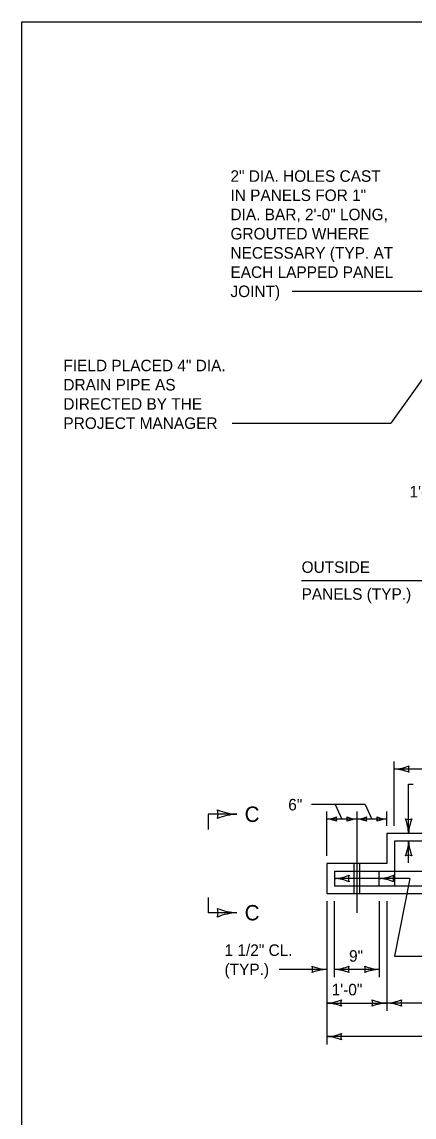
# Model space of a CAD drawing. Extents: x 49991.4 to 50021, y 49987.6 to 50011.4.
# Drawn here: x 49999.38 to 50001.43, y 49993.3 to 49999 of the extents above; entities that cross this region are included whole.
import ezdxf

# ---------------------------------------------------------------- set-up
doc = ezdxf.new("R2010")
doc.units = 0
for name, color, linetype in [('Level 1', 7, 'Continuous'), ('Level 2', 7, 'Continuous'), ('Level 3', 7, 'Continuous'), ('Level 4', 7, 'Continuous'), ('Level 5', 7, 'Continuous'), ('Level 6', 7, 'Continuous')]:
    doc.layers.add(name, color=color, linetype=linetype)

msp = doc.modelspace()

# ---------------------------------------------------------------- linework, layer by layer
at = {"layer": 'Level 1'}
for p, q in [((50003.3142, 49994.7753), (50001.283, 49994.7753)), ((50001.283, 49994.7753), (50001.283, 49994.619)), ((50001.323, 49994.7352), (50001.323, 49994.5029)), ((50003.2741, 49994.7352), (50001.323, 49994.7352)), ((50001.283, 49994.619), (50000.9705, 49994.619)), ((50000.9705, 49994.619), (50000.9705, 49994.4628)), ((50001.0105, 49994.579), (50001.0105, 49994.5029)), ((50001.0105, 49994.579), (50001.6735, 49994.579)), ((50001.2428, 49994.5029), (50001.2428, 49994.579)), ((50000.9705, 49994.4628), (50003.6267, 49994.4628)), ((50001.0105, 49994.5029), (50003.5866, 49994.5029))]:
    msp.add_line(p, q, dxfattribs=at)
msp.add_lwpolyline([(49999.3835, 49998.9992), (50016.7501, 49998.9992), (50016.7501, 49987.7988), (49999.3835, 49987.7988)], close=True, dxfattribs=at)
at = {"layer": 'Level 3'}
for p, q in [((50000.7897, 49997.5969), (50001.6157, 49997.5969)), ((50001.5149, 49997.2046), (50001.3035, 49996.9108)), ((50000.4775, 49996.9108), (50001.3035, 49996.9108)), ((50000.8395, 49996.0916), (50001.7038, 49996.0916)), ((50001.3223, 49994.8153), (50001.3223, 49995.1502)), ((50003.2753, 49995.1102), (50001.3223, 49995.1102)), ((50001.3969, 49995.031), (50001.42, 49995.031)), ((50001.3969, 49994.7753), (50001.3969, 49995.031)), ((50001.17, 49994.9252), (50000.8914, 49994.9252)), ((50001.0136, 49994.9252), (50001.0486, 49994.8502)), ((50001.17, 49994.9252), (50001.205, 49994.8502)), ((50000.9706, 49994.659), (50000.9706, 49994.8902)), ((50001.2832, 49994.8153), (50001.2832, 49994.8902)), ((50001.1268, 49994.8502), (50000.9706, 49994.8502)), ((50001.2832, 49994.8502), (50001.1268, 49994.8502)), ((50001.3969, 49994.6228), (50001.3969, 49994.7352)), ((50001.4028, 49994.541), (50001.0105, 49994.541)), ((50001.4028, 49994.541), (50001.323, 49994.1368)), ((50000.9705, 49994.4228), (50000.9705, 49993.6777)), ((50001.0097, 49994.4228), (50001.0097, 49994.0278)), ((50001.2441, 49994.4228), (50001.2441, 49994.0278)), ((50001.283, 49994.4228), (50001.283, 49993.8527)), ((50001.323, 49994.1368), (50001.5507, 49994.1368)), ((50000.9705, 49994.0678), (50000.7221, 49994.0678)), ((50001.2441, 49994.0678), (50001.0097, 49994.0678)), ((50000.9705, 49993.8927), (50001.283, 49993.8927)), ((50003.3142, 49993.8927), (50001.283, 49993.8927)), ((50003.6267, 49993.7177), (50000.9705, 49993.7177))]:
    msp.add_line(p, q, dxfattribs=at)
for centre, radius, start, end in [((50001.3131, 49995.3323), 0.2223, 272.3605, 292.544), ((50001.3108, 49994.8775), 0.233, 67.9228, 87.1727), ((50001.4505, 49995.1102), 0.0548, 162.1388, 197.8612), ((50000.3322, 49994.8754), 0.073, 342.1388, 17.8612), ((50000.5185, 49995.1857), 0.3107, 247.9228, 267.1727), ((50000.5154, 49994.5792), 0.2964, 92.3605, 112.544), ((50000.9645, 49994.9983), 0.1482, 272.3605, 292.544), ((50001.056, 49994.8502), 0.0365, 162.1388, 197.8612), ((50001.0413, 49994.8502), 0.0365, 342.1388, 17.8612), ((50001.1345, 49995.0053), 0.1553, 247.9228, 267.1727), ((50001.1207, 49994.9983), 0.1482, 272.3605, 292.544), ((50001.2123, 49994.8502), 0.0365, 162.1388, 197.8612), ((50001.1977, 49994.8502), 0.0365, 342.1388, 17.8612), ((50001.2908, 49995.0053), 0.1553, 247.9228, 267.1727), ((50000.9629, 49994.6951), 0.1553, 67.9228, 87.1727), ((50001.1329, 49994.7021), 0.1482, 92.3605, 112.544), ((50001.1191, 49994.6951), 0.1553, 67.9228, 87.1727), ((50001.2893, 49994.7021), 0.1482, 92.3605, 112.544), ((50001.3969, 49994.9035), 0.0548, 252.1388, 287.8612), ((50001.1642, 49994.7638), 0.233, 2.8273, 22.0772), ((50001.619, 49994.7661), 0.2223, 157.456, 177.6395), ((50001.1748, 49994.7444), 0.2223, 337.456, 357.6395), ((50001.6296, 49994.7467), 0.233, 182.8273, 202.0772), ((50001.3969, 49994.607), 0.0548, 72.1388, 107.8612), ((50001.0013, 49994.7631), 0.2223, 272.3605, 292.544), ((50000.999, 49994.3083), 0.233, 67.9228, 87.1727), ((50001.1387, 49994.541), 0.0548, 162.1388, 197.8612), ((50001.2336, 49994.7631), 0.2223, 272.3605, 292.544), ((50001.2313, 49994.3083), 0.233, 67.9228, 87.1727), ((50001.371, 49994.541), 0.0548, 162.1388, 197.8612), ((50000.3322, 49994.3628), 0.073, 342.1388, 17.8612), ((50000.5185, 49994.6731), 0.3107, 247.9228, 267.1727), ((50000.5154, 49994.0666), 0.2964, 92.3605, 112.544), ((50000.8423, 49994.0678), 0.0548, 342.1388, 17.8612), ((50000.982, 49994.3005), 0.233, 247.9228, 267.1727), ((50000.9797, 49993.8457), 0.2223, 92.3605, 112.544), ((50001.0005, 49994.2899), 0.2223, 272.3605, 292.544), ((50000.9982, 49993.8351), 0.233, 67.9228, 87.1727), ((50001.1379, 49994.0678), 0.0548, 162.1388, 197.8612), ((50001.1159, 49994.0678), 0.0548, 342.1388, 17.8612), ((50001.2556, 49994.3005), 0.233, 247.9228, 267.1727), ((50001.2533, 49993.8457), 0.2223, 92.3605, 112.544), ((50000.9613, 49994.1148), 0.2223, 272.3605, 292.544), ((50000.959, 49993.66), 0.233, 67.9228, 87.1727), ((50001.0987, 49993.8927), 0.0548, 162.1388, 197.8612), ((50001.2922, 49994.1148), 0.2223, 247.456, 267.6395), ((50001.1548, 49993.8927), 0.0548, 342.1388, 17.8612), ((50001.2945, 49993.66), 0.233, 92.8273, 112.0772), ((50001.2715, 49994.1254), 0.233, 272.8273, 292.0772), ((50001.2738, 49993.6706), 0.2223, 67.456, 87.6395), ((50001.4112, 49993.8927), 0.0548, 162.1388, 197.8612), ((50000.9613, 49993.9398), 0.2223, 272.3605, 292.544), ((50001.0987, 49993.7177), 0.0548, 162.1388, 197.8612), ((50000.959, 49993.485), 0.233, 67.9228, 87.1727)]:
    msp.add_arc(centre, radius, start, end, dxfattribs=at)
at = {"layer": 'Level 4'}
for p, q in [((50001.1111, 49994.619), (50001.1111, 49994.4628)), ((50001.1423, 49994.4628), (50001.1423, 49994.619))]:
    msp.add_line(p, q, dxfattribs=at)
at = {"layer": 'Level 5'}
msp.add_line((50001.1268, 49994.8902), (50001.1268, 49994.3628), dxfattribs=at)
at = {"layer": 'Level 6'}
for p, q in [((50000.5032, 49994.8754), (50000.3532, 49994.8754)), ((50000.3532, 49994.8754), (50000.3532, 49994.7954)), ((50000.3532, 49994.4428), (50000.3532, 49994.3628)), ((50000.5032, 49994.3628), (50000.3532, 49994.3628))]:
    msp.add_line(p, q, dxfattribs=at)

# ---------------------------------------------------------------- texts
at = {"layer": 'Level 2'}
for s, height, p in [('2" DIA. HOLES CAST', 0.06, (50000.4693, 49998.1669)), ('IN PANELS FOR 1"', 0.06, (50000.4693, 49998.0669)), ('DIA. BAR, 2\'-0" LONG,', 0.06, (50000.4693, 49997.9669)), ('GROUTED WHERE', 0.06, (50000.4693, 49997.8669)), ('NECESSARY (TYP. AT', 0.06, (50000.4693, 49997.7669)), ('EACH LAPPED PANEL', 0.06, (50000.4693, 49997.6669)), ('JOINT)', 0.06, (50000.4693, 49997.5669)), ('FIELD PLACED 4" DIA.', 0.06, (49999.5996, 49997.1808)), ('DRAIN PIPE AS ', 0.06, (49999.5996, 49997.0808)), ('DIRECTED BY THE', 0.06, (49999.5996, 49996.9808)), ('PROJECT MANAGER', 0.06, (49999.5996, 49996.8808)), ('1\'-0"', 0.06, (50001.4011, 49996.5241)), ('OUTSIDE', 0.06, (50000.8395, 49996.1316)), ('PANELS (TYP.)', 0.06, (50000.8395, 49995.9916)), ('C', 0.08, (50000.5432, 49994.8354)), ('6"', 0.06, (50000.7701, 49994.8952)), ('C', 0.08, (50000.5432, 49994.3228)), ('1 1/2" CL.', 0.06, (50000.4384, 49994.1378)), ('9"', 0.06, (50001.0866, 49994.1078)), ('(TYP.)', 0.06, (50000.4384, 49994.0378)), ('1\'-0"', 0.06, (50000.9961, 49993.9327))]:
    msp.add_text(s, height=height, dxfattribs=at).set_placement(p)

doc.saveas('drawing.dxf')
